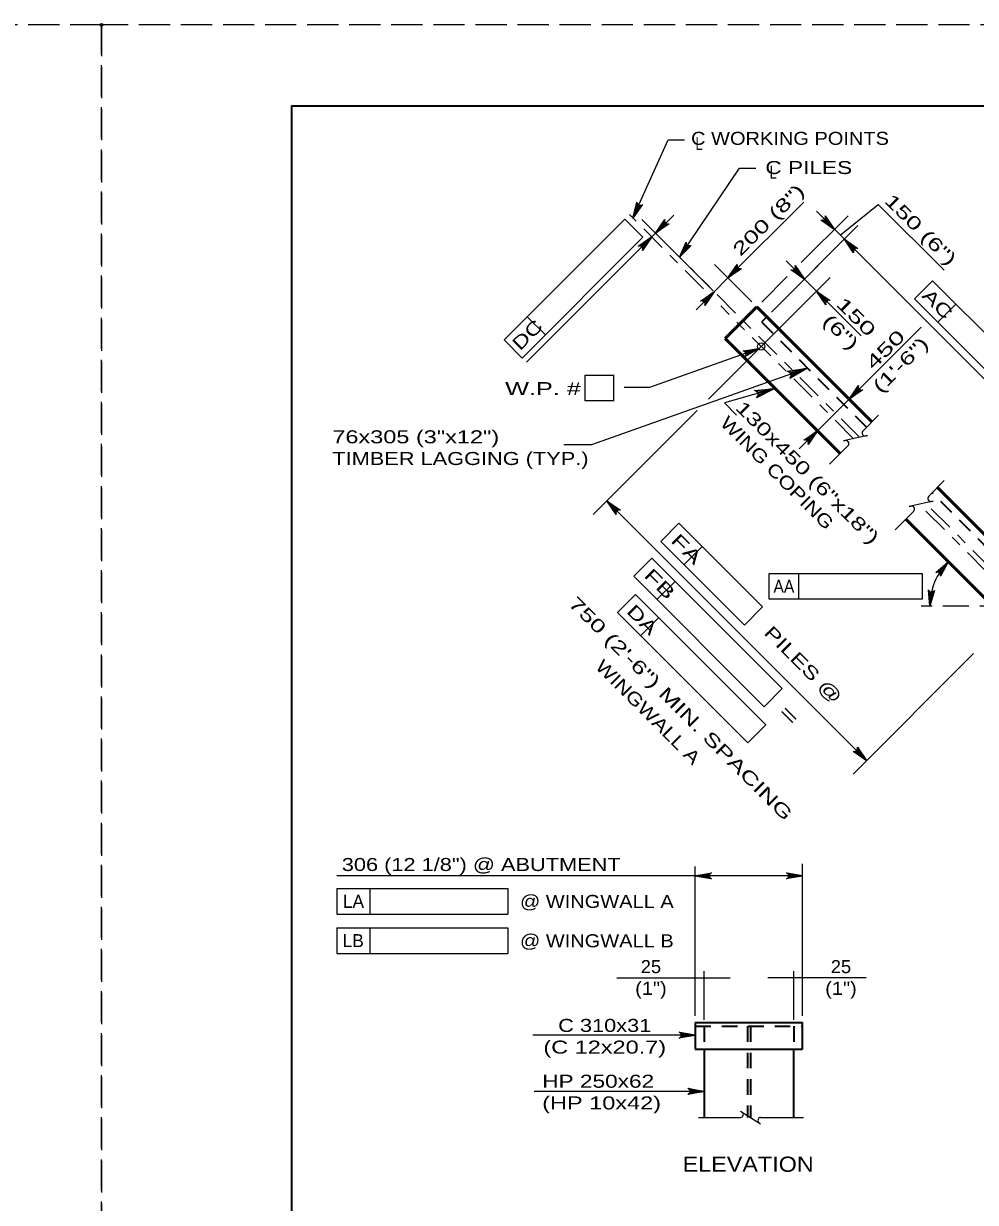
# Model space of a CAD drawing. Extents: x -6.4 to 73.1, y -66 to 0.
# Drawn here: x 33.28 to 42.06, y -10.86 to 0.01 of the extents above; entities that cross this region are included whole.
import ezdxf
from ezdxf.enums import TextEntityAlignment as Align

# ---------------------------------------------------------------- set-up
doc = ezdxf.new("R2010")
doc.units = 0
doc.header["$LTSCALE"] = 0.048
doc.header["$PDMODE"] = 32
doc.header["$PDSIZE"] = 0.024
for name, pattern in [('DOT_DASHED', [7.7, 5, -1.2, 0.3, -1.2]), ('LONG_DASHED', [7.5, 6, -1.5]), ('MEDIUM_DASHED', [4.5, 3, -1.5])]:
    doc.linetypes.add(name, pattern=pattern)
for name, color, linetype, lineweight in [('1', 7, 'Continuous', 13), ('2', 7, 'Continuous', 53), ('3', 7, 'Continuous', 35), ('4', 7, 'Continuous', 25), ('5', 7, 'Continuous', 25), ('52', 7, 'Continuous', 25), ('63', 7, 'LONG_DASHED', 13), ('8', 7, 'Continuous', 25)]:
    doc.layers.add(name, color=color, linetype=linetype, lineweight=lineweight)
doc.layers.add('62', color=7, linetype='Continuous')

msp = doc.modelspace()

# ---------------------------------------------------------------- hatches: boundary and pattern name
at = {"layer": '4'}
for points in [[(38.9, -1.78175), (38.95733, -1.678), (38.93942, -1.67)], [(39.17808, -1.823), (39.20592, -1.85083), (39.10842, -1.92042)], [(40.68925, -1.78775), (40.66142, -1.81558), (40.75883, -1.88517)], [(38.97617, -2.02492), (39.004, -2.05275), (39.07358, -1.95533)], [(39.32958, -2.14158), (39.40367, -2.04908), (39.38733, -2.03808)], [(40.94675, -2.04525), (40.91892, -2.07308), (40.84933, -1.97567)], [(39.846, -2.236), (39.87383, -2.26383), (39.77642, -2.33342)], [(40.41158, -2.24642), (40.38375, -2.27425), (40.48117, -2.34383)], [(39.5515, -2.5305), (39.57933, -2.55833), (39.64892, -2.46092)], [(40.68992, -2.52475), (40.66208, -2.55267), (40.5925, -2.45517)], [(40.06517, -2.98258), (39.95058, -3.01292), (39.95717, -3.03142)], [(40.50925, -3.16367), (40.39467, -3.194), (40.40125, -3.2125)], [(40.96308, -3.35308), (40.99092, -3.38092), (40.8935, -3.4505)], [(40.50375, -3.81242), (40.53158, -3.84025), (40.60117, -3.74283)], [(38.75692, -4.45783), (38.72908, -4.48567), (38.6595, -4.38825)], [(40.98517, -6.686), (40.95733, -6.71392), (41.05475, -6.7835)]]:
    msp.add_hatch(color=256, dxfattribs=at).paths.add_polyline_path(points)

# ---------------------------------------------------------------- linework, layer by layer
at = {"layer": '1', "lineweight": 35}
msp.add_lwpolyline([(35.75, -21.25), (67.25, -21.25), (67.25, -0.75), (35.75, -0.75)], close=True, dxfattribs=at)
at = {"layer": '2'}
for p, q in [((40.0435, -2.6005), (39.75117, -2.89283)), ((41.10333, -3.66042), (40.0435, -2.6005)), ((40.81108, -3.95267), (39.75117, -2.89283)), ((42.50767, -5.06467), (41.70775, -4.26483)), ((42.33642, -5.47808), (41.4155, -4.55708))]:
    msp.add_line(p, q, dxfattribs=at)
at = {"layer": '3'}
for p, q in [((40.134, -2.691), (40.08525, -2.73975)), ((39.475, -9.19783), (39.475, -9.44383)), ((39.475, -9.19783), (40.46467, -9.19783)), ((40.46467, -9.44383), (40.46467, -9.19783)), ((39.475, -9.44383), (40.46467, -9.44383)), ((39.557, -9.44383), (39.557, -10.07258)), ((40.38267, -10.07258), (40.38267, -9.44383))]:
    msp.add_line(p, q, dxfattribs=at)
at = {"layer": '3', "linetype": 'MEDIUM_DASHED'}
for p, q in [((41.05467, -3.70908), (40.08525, -2.73975)), ((42.70317, -5.36), (41.65908, -4.3135)), ((39.475, -9.23225), (40.46467, -9.23225)), ((39.557, -9.23225), (39.557, -9.44383)), ((39.95608, -9.23225), (39.95608, -10.07258)), ((39.98358, -9.23225), (39.98358, -10.07258)), ((40.38267, -9.23225), (40.38267, -9.44383))]:
    msp.add_line(p, q, dxfattribs=at)
at = {"layer": '3', "lineweight": 25}
for p, q in [((39.50367, -10.07258), (39.89075, -10.07258)), ((39.89283, -10.0145), (40.07758, -10.13067)), ((40.07717, -10.07258), (40.47267, -10.07258))]:
    msp.add_line(p, q, dxfattribs=at)
for centre, start, end in [((39.89071, -10.04532), 270, 60), ((40.07972, -10.09976), 95.32859, 237.86724)]:
    msp.add_arc(centre, 0.02728, start, end, dxfattribs=at)
at = {"layer": '4'}
for p, q in [((38.9, -1.78175), (39.22425, -1.05992)), ((39.22425, -1.05992), (39.37508, -1.05992)), ((39.32958, -2.14158), (39.88225, -1.31983)), ((39.88225, -1.31983), (40.0325, -1.31983)), ((39.77642, -2.33342), (40.47583, -1.634)), ((40.84933, -1.97567), (40.59183, -1.71817)), ((40.81133, -1.93775), (41.16217, -1.655)), ((41.16217, -1.655), (41.7685, -2.26125)), ((37.71175, -2.90475), (38.82533, -1.79117)), ((38.82533, -1.79117), (38.99233, -1.95825)), ((39.64083, -2.45283), (38.98317, -1.79517)), ((39.1085, -1.92042), (39.2755, -1.75342)), ((40.45242, -2.19158), (40.88408, -1.75992)), ((40.75883, -1.88517), (40.65442, -1.78083)), ((39.07358, -1.95533), (37.91792, -3.11092)), ((39.10842, -1.92042), (39.07358, -1.95533)), ((40.1775, -2.6475), (40.97458, -1.85042)), ((37.87883, -3.07183), (38.99233, -1.95825)), ((43.223, -4.34933), (40.84933, -1.97567)), ((40.96067, -2.087), (41.04417, -2.17058)), ((39.99567, -2.55267), (39.65117, -2.20817)), ((40.1775, -2.6475), (40.60642, -2.21858)), ((40.48117, -2.34383), (40.31417, -2.17683)), ((40.71775, -2.32992), (39.59808, -3.44967)), ((39.64892, -2.46092), (39.77642, -2.33342)), ((40.087, -2.557), (40.32325, -2.32075)), ((40.48117, -2.34383), (40.5925, -2.45517)), ((41.6635, -2.35983), (41.4965, -2.52683)), ((41.6635, -2.35983), (42.86617, -3.5625)), ((39.64892, -2.46092), (39.48192, -2.62792)), ((40.5925, -2.45517), (41.00375, -2.8665)), ((41.4965, -2.52683), (42.69908, -3.7295)), ((41.87733, -2.57367), (41.71033, -2.74075)), ((37.92567, -2.69092), (38.09267, -2.85792)), ((40.8935, -3.4505), (41.55792, -2.78592)), ((37.71175, -2.90475), (37.87883, -3.07183)), ((38.46083, -3.23067), (38.7245, -3.23067)), ((38.46083, -3.46683), (38.46083, -3.23067)), ((38.7245, -3.46683), (38.7245, -3.23067)), ((38.7245, -3.46683), (38.46083, -3.46683)), ((40.60117, -3.74283), (40.8935, -3.4505)), ((40.87592, -3.43292), (41.01875, -3.57575)), ((39.491, -3.55667), (38.53425, -4.5135)), ((40.60117, -3.74283), (40.43417, -3.90983)), ((40.58358, -3.72525), (40.72642, -3.86808)), ((41.05475, -6.7835), (38.6595, -4.38825)), ((39.324, -4.59475), (39.157, -4.76183)), ((39.324, -4.59475), (40.09583, -5.36667)), ((39.157, -4.76183), (39.92883, -5.53367)), ((39.53783, -4.80867), (39.37083, -4.97567)), ((39.0745, -4.91725), (38.9075, -5.08425)), ((39.0745, -4.91725), (40.27717, -6.11992)), ((38.9075, -5.08425), (40.11008, -6.28692)), ((40.15475, -5.05925), (41.56675, -5.05925)), ((40.15475, -5.2955), (40.15475, -5.05925)), ((40.4285, -5.2955), (40.4285, -5.05925)), ((41.56675, -5.05925), (41.56675, -5.2955)), ((39.28833, -5.13108), (39.12133, -5.29817)), ((38.92342, -5.25075), (38.75642, -5.41775)), ((38.92342, -5.25075), (40.12608, -6.45333)), ((41.56675, -5.2955), (40.15475, -5.2955)), ((38.75642, -5.41775), (39.95908, -6.62042)), ((40.09583, -5.36667), (39.92883, -5.53367)), ((39.13733, -5.46458), (38.97025, -5.63158)), ((42.04167, -5.79658), (40.9295, -6.90875)), ((40.27717, -6.11992), (40.11008, -6.28692)), ((40.12608, -6.45333), (39.95908, -6.62042)), ((39.475, -9.13783), (39.475, -7.75883)), ((40.46467, -9.13783), (40.46467, -7.73392)), ((39.475, -7.846), (36.17042, -7.846)), ((40.46467, -7.846), (39.475, -7.846)), ((36.17042, -7.96292), (37.74525, -7.96292)), ((36.17042, -7.96292), (36.17042, -8.19908)), ((36.47292, -7.96292), (36.47292, -8.19908)), ((37.74525, -7.96292), (37.74525, -8.19908)), ((36.17042, -8.19908), (37.74525, -8.19908)), ((36.17042, -8.32533), (37.74525, -8.32533)), ((36.17042, -8.32533), (36.17042, -8.56158)), ((36.47292, -8.32533), (36.47292, -8.56158)), ((37.74525, -8.32533), (37.74525, -8.56158)), ((36.17042, -8.56158), (37.74525, -8.56158)), ((38.75075, -8.78517), (39.797, -8.78517)), ((39.557, -9.17225), (39.557, -8.72517)), ((41.04925, -8.78517), (40.14267, -8.78517)), ((40.38267, -9.17225), (40.38267, -8.72517)), ((39.475, -9.31558), (37.97583, -9.31558)), ((39.557, -9.83267), (37.989, -9.83267))]:
    msp.add_line(p, q, dxfattribs=at)
at = {"layer": '4', "linetype": 'DOT_DASHED'}
for p, q in [((39.55167, -2.43342), (38.86742, -1.74917)), ((40.9905, -3.8025), (39.3905, -2.2025)), ((40.93367, -3.81542), (39.70958, -2.59133)), ((42.53525, -5.417), (41.53792, -4.41967)), ((42.58425, -5.39617), (41.59467, -4.40667)), ((53.33858, -5.36), (41.53183, -5.36))]:
    msp.add_line(p, q, dxfattribs=at)
at = {"layer": '4'}
for points in [[(38.9, -1.78175), (38.93558, -1.63425), (38.93817, -1.648), (38.94483, -1.6575), (38.95325, -1.66317), (38.96308, -1.66567), (38.97467, -1.66442), (38.98658, -1.65717), (38.9, -1.78175), (38.97467, -1.66442), (38.96308, -1.66567), (38.9, -1.78175), (38.95325, -1.66317), (38.94483, -1.6575), (38.9, -1.78175), (38.93817, -1.648)], [(39.1085, -1.92042), (39.19417, -1.79517), (39.19167, -1.80892), (39.19458, -1.82025), (39.20042, -1.8285), (39.20867, -1.83433), (39.22, -1.83725), (39.23375, -1.83475), (39.1085, -1.92042), (39.22, -1.83725), (39.20867, -1.83433), (39.1085, -1.92042), (39.20042, -1.8285), (39.19458, -1.82025), (39.1085, -1.92042), (39.19167, -1.80892)], [(40.75883, -1.88517), (40.63358, -1.7995), (40.64733, -1.802), (40.65858, -1.79917), (40.66683, -1.79325), (40.67275, -1.785), (40.67558, -1.77375), (40.67308, -1.76), (40.75883, -1.88517), (40.67558, -1.77375), (40.67275, -1.785), (40.75883, -1.88517), (40.66683, -1.79325), (40.65858, -1.79917), (40.75883, -1.88517), (40.64733, -1.802)], [(39.07358, -1.95533), (38.98792, -2.08058), (38.99042, -2.06683), (38.9875, -2.0555), (38.98167, -2.04725), (38.97333, -2.04142), (38.96208, -2.0385), (38.94833, -2.041), (39.07358, -1.95533), (38.96208, -2.0385), (38.97333, -2.04142), (39.07358, -1.95533), (38.98167, -2.04725), (38.9875, -2.0555), (39.07358, -1.95533), (38.99042, -2.06683)], [(39.32958, -2.14158), (39.38958, -2.00225), (39.38983, -2.01625), (39.39483, -2.02667), (39.40217, -2.03375), (39.41142, -2.03783), (39.423, -2.0385), (39.436, -2.03342), (39.32958, -2.14158), (39.423, -2.0385), (39.41142, -2.03783), (39.32958, -2.14158), (39.40217, -2.03375), (39.39483, -2.02667), (39.32958, -2.14158), (39.38983, -2.01625)], [(40.84933, -1.97567), (40.97458, -2.06133), (40.96083, -2.05883), (40.9495, -2.06175), (40.94125, -2.06758), (40.93542, -2.07583), (40.9325, -2.08717), (40.935, -2.10092), (40.84933, -1.97567), (40.9325, -2.08717), (40.93542, -2.07583), (40.84933, -1.97567), (40.94125, -2.06758), (40.9495, -2.06175), (40.84933, -1.97567), (40.96083, -2.05883)], [(39.77642, -2.33342), (39.86208, -2.20817), (39.85958, -2.22192), (39.8625, -2.23325), (39.86833, -2.2415), (39.87658, -2.24733), (39.88792, -2.25025), (39.90167, -2.24775), (39.77642, -2.33342), (39.88792, -2.25025), (39.87658, -2.24733), (39.77642, -2.33342), (39.86833, -2.2415), (39.8625, -2.23325), (39.77642, -2.33342), (39.85958, -2.22192)], [(40.48117, -2.34383), (40.35592, -2.25817), (40.36967, -2.26067), (40.381, -2.25775), (40.38925, -2.25192), (40.39508, -2.24367), (40.398, -2.23233), (40.3955, -2.21858), (40.48117, -2.34383), (40.398, -2.23233), (40.39508, -2.24367), (40.48117, -2.34383), (40.38925, -2.25192), (40.381, -2.25775), (40.48117, -2.34383), (40.36967, -2.26067)], [(39.64892, -2.46092), (39.56325, -2.58617), (39.56575, -2.57242), (39.56283, -2.56108), (39.557, -2.55283), (39.54875, -2.547), (39.53742, -2.54408), (39.52367, -2.54658), (39.64892, -2.46092), (39.53742, -2.54408), (39.54875, -2.547), (39.64892, -2.46092), (39.557, -2.55283), (39.56283, -2.56108), (39.64892, -2.46092), (39.56575, -2.57242)], [(40.5925, -2.45517), (40.71775, -2.54083), (40.704, -2.53833), (40.69267, -2.54125), (40.68442, -2.54708), (40.67858, -2.55542), (40.67567, -2.56667), (40.67817, -2.58042), (40.5925, -2.45517), (40.67567, -2.56667), (40.67858, -2.55542), (40.5925, -2.45517), (40.68442, -2.54708), (40.69267, -2.54125), (40.5925, -2.45517), (40.704, -2.53833)], [(40.06517, -2.98258), (39.05133, -3.3435), (38.81917, -3.3435)], [(40.06517, -2.98258), (39.93408, -3.05892), (39.94217, -3.04758), (39.94442, -3.03617), (39.94267, -3.02617), (39.93775, -3.01733), (39.92875, -3.00992), (39.91533, -3.00625), (40.06517, -2.98258), (39.92875, -3.00992), (39.93775, -3.01733), (40.06517, -2.98258), (39.94267, -3.02617), (39.94442, -3.03617), (40.06517, -2.98258), (39.94217, -3.04758)], [(40.50925, -3.16367), (38.51642, -3.87208), (38.263, -3.87208)], [(40.20917, -3.3525), (39.74433, -3.48608), (39.85542, -3.59708)], [(40.8935, -3.4505), (40.97917, -3.32525), (40.97667, -3.339), (40.97958, -3.35025), (40.98542, -3.35858), (40.99367, -3.36442), (41.005, -3.36733), (41.01875, -3.36483), (40.8935, -3.4505), (41.005, -3.36733), (40.99367, -3.36442), (40.8935, -3.4505), (40.98542, -3.35858), (40.97958, -3.35025), (40.8935, -3.4505), (40.97667, -3.339)], [(40.60117, -3.74283), (40.5155, -3.86808), (40.518, -3.85433), (40.51508, -3.843), (40.50925, -3.83475), (40.501, -3.82892), (40.48967, -3.826), (40.47592, -3.8285), (40.60117, -3.74283), (40.48967, -3.826), (40.501, -3.82892), (40.60117, -3.74283), (40.50925, -3.83475), (40.51508, -3.843), (40.60117, -3.74283), (40.518, -3.85433)], [(38.6595, -4.38825), (38.78475, -4.47392), (38.771, -4.47142), (38.75967, -4.47433), (38.75142, -4.48017), (38.74558, -4.48842), (38.74267, -4.49975), (38.74517, -4.5135), (38.6595, -4.38825), (38.74267, -4.49975), (38.74558, -4.48842), (38.6595, -4.38825), (38.75142, -4.48017), (38.75967, -4.47433), (38.6595, -4.38825), (38.771, -4.47142)], [(41.80758, -4.94917), (41.73575, -5.08283), (41.73683, -5.06892), (41.73267, -5.058), (41.726, -5.05033), (41.71708, -5.0455), (41.70558, -5.04375), (41.69217, -5.04775), (41.80758, -4.94917), (41.70558, -5.04375), (41.71708, -5.0455), (41.80758, -4.94917), (41.726, -5.05033), (41.73267, -5.058), (41.80758, -4.94917), (41.73683, -5.06892)], [(41.63742, -5.36), (41.62533, -5.20867), (41.63208, -5.221), (41.64142, -5.22792), (41.65117, -5.23075), (41.66133, -5.23008), (41.67192, -5.22525), (41.681, -5.21467), (41.63742, -5.36), (41.67192, -5.22525), (41.66133, -5.23008), (41.63742, -5.36), (41.65117, -5.23075), (41.64142, -5.22792), (41.63742, -5.36), (41.63208, -5.221)], [(41.05475, -6.7835), (40.9295, -6.69783), (40.94325, -6.70033), (40.95458, -6.69742), (40.96283, -6.69158), (40.96867, -6.68333), (40.97158, -6.672), (40.96908, -6.65825), (41.05475, -6.7835), (40.97158, -6.672), (40.96867, -6.68333), (41.05475, -6.7835), (40.96283, -6.69158), (40.95458, -6.69742), (41.05475, -6.7835), (40.94325, -6.70033)], [(39.475, -7.846), (39.62417, -7.818), (39.61842, -7.822), (39.61267, -7.826), (39.60967, -7.831), (39.60675, -7.836), (39.60583, -7.841), (39.605, -7.846), (39.60583, -7.851), (39.60675, -7.856), (39.60967, -7.861), (39.61267, -7.866), (39.61842, -7.87), (39.62417, -7.874), (39.475, -7.846), (39.61842, -7.87), (39.61267, -7.866), (39.475, -7.846), (39.60967, -7.861), (39.60675, -7.856), (39.475, -7.846), (39.60583, -7.851), (39.605, -7.846), (39.475, -7.846), (39.60583, -7.841), (39.60675, -7.836), (39.475, -7.846), (39.60967, -7.831), (39.61267, -7.826), (39.475, -7.846), (39.61842, -7.822)], [(40.46467, -7.846), (40.3155, -7.874), (40.32125, -7.87), (40.327, -7.866), (40.33, -7.861), (40.33292, -7.856), (40.33383, -7.851), (40.33467, -7.846), (40.33383, -7.841), (40.33292, -7.836), (40.33, -7.831), (40.327, -7.826), (40.32125, -7.822), (40.3155, -7.818), (40.46467, -7.846), (40.32125, -7.822), (40.327, -7.826), (40.46467, -7.846), (40.33, -7.831), (40.33292, -7.836), (40.46467, -7.846), (40.33383, -7.841), (40.33467, -7.846), (40.46467, -7.846), (40.33383, -7.851), (40.33292, -7.856), (40.46467, -7.846), (40.33, -7.861), (40.327, -7.866), (40.46467, -7.846), (40.32125, -7.87)], [(39.475, -9.31558), (39.32583, -9.34358), (39.33158, -9.33958), (39.33733, -9.33558), (39.34033, -9.33058), (39.34325, -9.32558), (39.34417, -9.32058), (39.345, -9.31558), (39.34417, -9.31058), (39.34325, -9.30558), (39.34033, -9.30058), (39.33733, -9.29558), (39.33158, -9.29158), (39.32583, -9.28767), (39.475, -9.31558), (39.33158, -9.29158), (39.33733, -9.29558), (39.475, -9.31558), (39.34033, -9.30058), (39.34325, -9.30558), (39.475, -9.31558), (39.34417, -9.31058), (39.345, -9.31558), (39.475, -9.31558), (39.34417, -9.32058), (39.34325, -9.32558), (39.475, -9.31558), (39.34033, -9.33058), (39.33733, -9.33558), (39.475, -9.31558), (39.33158, -9.33958)], [(39.557, -9.83267), (39.40783, -9.86067), (39.41358, -9.85667), (39.41933, -9.85267), (39.42233, -9.84767), (39.42525, -9.84267), (39.42617, -9.83767), (39.427, -9.83267), (39.42617, -9.82767), (39.42525, -9.82267), (39.42233, -9.81767), (39.41933, -9.81267), (39.41358, -9.80867), (39.40783, -9.80475), (39.557, -9.83267), (39.41358, -9.80867), (39.41933, -9.81267), (39.557, -9.83267), (39.42233, -9.81767), (39.42525, -9.82267), (39.557, -9.83267), (39.42617, -9.82767), (39.427, -9.83267), (39.557, -9.83267), (39.42617, -9.83767), (39.42525, -9.84267), (39.557, -9.83267), (39.42233, -9.84767), (39.41933, -9.85267), (39.557, -9.83267), (39.41358, -9.85667)]]:
    msp.add_lwpolyline(points, dxfattribs=at)
for points in [[(38.9, -1.78175), (38.95733, -1.678), (38.93942, -1.67)], [(39.17808, -1.823), (39.20592, -1.85083), (39.10842, -1.92042)], [(40.68925, -1.78775), (40.66142, -1.81558), (40.75883, -1.88517)], [(38.97617, -2.02492), (39.004, -2.05275), (39.07358, -1.95533)], [(39.32958, -2.14158), (39.40367, -2.04908), (39.38733, -2.03808)], [(40.94675, -2.04525), (40.91892, -2.07308), (40.84933, -1.97567)], [(39.846, -2.236), (39.87383, -2.26383), (39.77642, -2.33342)], [(40.41158, -2.24642), (40.38375, -2.27425), (40.48117, -2.34383)], [(39.5515, -2.5305), (39.57933, -2.55833), (39.64892, -2.46092)], [(40.68992, -2.52475), (40.66208, -2.55267), (40.5925, -2.45517)], [(40.06517, -2.98258), (39.95058, -3.01292), (39.95717, -3.03142)], [(40.50925, -3.16367), (40.39467, -3.194), (40.40125, -3.2125)], [(40.96308, -3.35308), (40.99092, -3.38092), (40.8935, -3.4505)], [(40.50375, -3.81242), (40.53158, -3.84025), (40.60117, -3.74283)], [(38.75692, -4.45783), (38.72908, -4.48567), (38.6595, -4.38825)], [(40.98517, -6.686), (40.95733, -6.71392), (41.05475, -6.7835)]]:
    msp.add_lwpolyline(points, close=True, dxfattribs=at)
msp.add_circle((40.08298, -2.96472), 0.03402, dxfattribs=at)
msp.add_arc((42.21835, -5.35998), 0.58095, 134.99887, 180.00148, dxfattribs=at)
at = {"layer": '52'}
for points in [[(40.50925, -3.16367), (40.34533, -3.25908), (40.3555, -3.24483), (40.35833, -3.23058), (40.35617, -3.21808), (40.34992, -3.207), (40.33875, -3.19775), (40.32192, -3.19317), (40.50925, -3.16367), (40.33875, -3.19775), (40.34992, -3.207), (40.50925, -3.16367), (40.35617, -3.21808), (40.35833, -3.23058), (40.50925, -3.16367), (40.3555, -3.24483)], [(40.20917, -3.3525), (40.03967, -3.43758), (40.05067, -3.42408), (40.05433, -3.41), (40.053, -3.39742), (40.0475, -3.386), (40.03692, -3.376), (40.02033, -3.37042), (40.20917, -3.3525), (40.03692, -3.376), (40.0475, -3.386), (40.20917, -3.3525), (40.053, -3.39742), (40.05433, -3.41), (40.20917, -3.3525), (40.05067, -3.42408)]]:
    msp.add_lwpolyline(points, dxfattribs=at)
at = {"layer": '62'}
msp.add_point((34, 0), dxfattribs=at)
at = {"layer": '63'}
for points in [[(0, -22), (34, -22), (34, 0), (0, 0)], [(34, -22), (68, -22), (68, 0), (34, 0)]]:
    msp.add_lwpolyline(points, close=True, dxfattribs=at)
at = {"layer": '8'}
for p, q in [((41.16567, -3.59808), (41.02225, -3.7415)), ((40.88483, -3.87892), (40.71208, -4.05167)), ((41.77042, -4.20217), (41.627, -4.34558)), ((41.48967, -4.48292), (41.31683, -4.65575))]:
    msp.add_line(p, q, dxfattribs=at)
for points in [[(41.04967, -3.78908), (41.06342, -3.78583), (40.84183, -3.83642), (40.85667, -3.83308)], [(41.65442, -4.39308), (41.66817, -4.38992), (41.44658, -4.44042), (41.46142, -4.43708)]]:
    msp.add_lwpolyline(points, dxfattribs=at)
for centre, start, end in [((41.04232, -3.76162), 135, 285), ((40.863, -3.86074), 320.32859, 102.86724), ((41.64709, -4.36567), 135, 285), ((41.46778, -4.46479), 320.32859, 102.86724)]:
    msp.add_arc(centre, 0.02841, start, end, dxfattribs=at)

# ---------------------------------------------------------------- texts
at = {"layer": '4'}
for s, width, p in [('C WORKING POINTS', 1.15, (39.43575, -1.10617)), ('L', 0.75, (39.47675, -1.15408)), ('C PILES', 1.3, (40.12108, -1.37525)), ('L', 0.75, (40.16058, -1.41833)), ('HP 250x62', 1.3, (38.06333, -9.79942)), ('(HP 10x42)', 1.35, (38.06333, -9.99942))]:
    msp.add_text(s, height=0.12, dxfattribs=dict(at, width=width)).set_placement(p)
for s, rotation, width, p in [('200 (8")', 45, 1.5, (40.19149, -1.84051)), ('AC', 314.938, 1.4, (41.6673, -2.61562)), ('DC', 45, 1.35, (37.96903, -2.89947)), ('FA', 314.938, 1.55, (39.35213, -4.87495)), ('FB', 314.938, 1.55, (39.10505, -5.19629)), ('750 (2\'-6") MIN. SPACING', 315, 1.5, (39.29866, -6.34624)), ('DA', 314.938, 1.4, (38.94379, -5.52654)), ('PILES @', 314.938, 1.4, (40.42788, -5.94149)), ('WINGWALL A', 315, 1.25, (38.99691, -6.37774)), ('=', 314.938, 1.85, (40.29778, -6.40699))]:
    msp.add_text(s, height=0.12, rotation=rotation, dxfattribs=dict(at, width=width)).set_placement(p, align=Align.CENTER)
for s, height, width, p in [('W.P. # ', 0.12, 1.45, (38.10321, -3.41367)), ('AA', 0.12, 0.9, (40.29192, -5.23617)), ('306 (12 1/8") @ ABUTMENT', 0.12, 1.25, (37.50092, -7.80125)), ('25', 0.12, 1.05, (39.06583, -8.74283)), ('25', 0.12, 1.05, (40.81825, -8.74283)), ('(1")', 0.12, 1.15, (39.06583, -8.94283)), ('(1")', 0.12, 1.15, (40.81825, -8.94283)), ('C 310x31', 0.12, 1.25, (38.63987, -9.28475)), ('(C 12x20.7)', 0.12, 1.35, (38.63992, -9.48475)), ('ELEVATION', 0.14, 1.15, (39.96262, -10.57442))]:
    msp.add_text(s, height=height, dxfattribs=dict(at, width=width)).set_placement(p, align=Align.CENTER)
for s, p in [('LA', (36.32271, -8.14083)), ('LB', (36.32029, -8.50333))]:
    msp.add_text(s, height=0.12, dxfattribs=at).set_placement(p, align=Align.CENTER)
at = {"layer": '4', "width": 1.15}
for s, p in [('@ WINGWALL A', (37.858, -8.14092)), ('@ WINGWALL B', (37.858, -8.50333))]:
    msp.add_text(s, height=0.12, rotation=359.938, dxfattribs=at).set_placement(p)
at = {"layer": '5'}
for s, width, p in [('150 (6")', 1.5, (41.21108, -1.63)), ('130x450 (6"x18")', 1.45, (39.83633, -3.53933)), ('WING COPING', 1.25, (39.69492, -3.68075))]:
    msp.add_text(s, height=0.12, rotation=315, dxfattribs=dict(at, width=width)).set_placement(p)
for s, rotation, width, p in [('150', 315, 1.6, (40.91574, -2.73332)), ('(6")', 315, 1.5, (40.77441, -2.87482)), ('450', 45, 1.6, (41.26849, -3.03526)), ('(1\'-6")', 45, 1.5, (41.40991, -3.17668))]:
    msp.add_text(s, height=0.12, rotation=rotation, dxfattribs=dict(at, width=width)).set_placement(p, align=Align.CENTER)
for s, width, p in [('76x305 (3"x12")', 1.35, (36.12792, -3.858)), ('TIMBER LAGGING (TYP.)', 1.25, (36.12792, -4.058))]:
    msp.add_text(s, height=0.12, dxfattribs=dict(at, width=width)).set_placement(p)

doc.saveas('drawing.dxf')
